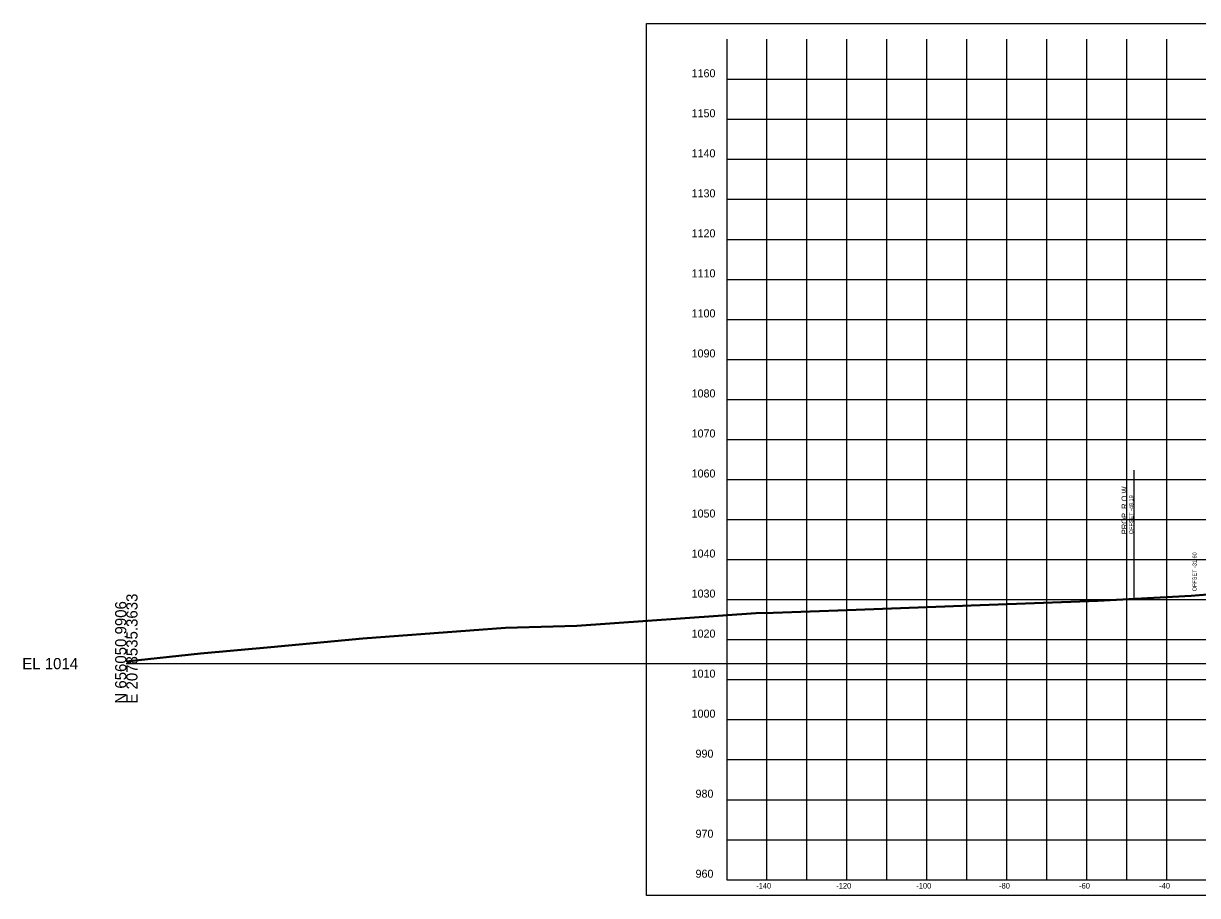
# Model space of a CAD drawing. Extents: x 1131015 to 1136271, y 133453 to 174329.
# Drawn here: x 1131014.8 to 1131308.1, y 155109.7 to 155327.6 of the extents above; entities that cross this region are included whole.
import ezdxf

# ---------------------------------------------------------------- set-up
doc = ezdxf.new("R2010")
doc.units = 0
for name, color, linetype in [('DESIGN - ROW - Right-of-Way and Easement Labels', 7, 'Continuous'), ('DESIGN - ROW - Right-of-Way Linework', 7, 'Continuous'), ('DESIGN - SHEET - Corner Text', 7, 'Continuous'), ('DESIGN - SHEET - Light Grid', 7, 'Continuous'), ('DESIGN - SHEET - Linework', 7, 'Continuous'), ('DESIGN - SHEET - Plot Shape', 7, 'Continuous'), ('DESIGN - TYPICAL - Slope Tie Text', 7, 'Continuous'), ('SURVEY - GROUND - Bottom of Topsoil Layer', 7, 'Continuous'), ('SURVEY - GROUND - Top of Ground', 7, 'Continuous')]:
    doc.layers.add(name, color=color, linetype=linetype)

msp = doc.modelspace()

# ---------------------------------------------------------------- linework, layer by layer
at = {"layer": 'DESIGN - ROW - Right-of-Way Linework'}
msp.add_line((1131292.27, 155183.98), (1131292.27, 155215.98), dxfattribs=at)
at = {"layer": 'DESIGN - SHEET - Light Grid'}
msp.add_line((1131040.46, 155167.66), (1131340.46, 155167.66), dxfattribs=at)
at = {"layer": 'DESIGN - SHEET - Linework'}
for p, q in [((1131200.46, 155113.66), (1131200.46, 155323.66)), ((1131210.46, 155113.66), (1131210.46, 155323.66)), ((1131220.46, 155113.66), (1131220.46, 155323.66)), ((1131230.46, 155113.66), (1131230.46, 155323.66)), ((1131240.46, 155113.66), (1131240.46, 155323.66)), ((1131250.46, 155113.66), (1131250.46, 155323.66)), ((1131260.46, 155113.66), (1131260.46, 155323.66)), ((1131270.46, 155113.66), (1131270.46, 155323.66)), ((1131280.46, 155113.66), (1131280.46, 155323.66)), ((1131290.46, 155113.66), (1131290.46, 155323.66)), ((1131300.46, 155113.66), (1131300.46, 155323.66)), ((1131190.46, 155313.66), (1131490.46, 155313.66)), ((1131190.46, 155303.66), (1131490.46, 155303.66)), ((1131190.46, 155293.66), (1131490.46, 155293.66)), ((1131190.46, 155283.66), (1131490.46, 155283.66)), ((1131190.46, 155273.66), (1131490.46, 155273.66)), ((1131190.46, 155263.66), (1131490.46, 155263.66)), ((1131190.46, 155253.66), (1131490.46, 155253.66)), ((1131190.46, 155243.66), (1131490.46, 155243.66)), ((1131190.46, 155233.66), (1131490.46, 155233.66)), ((1131190.46, 155223.66), (1131490.46, 155223.66)), ((1131190.46, 155213.66), (1131490.46, 155213.66)), ((1131190.46, 155203.66), (1131490.46, 155203.66)), ((1131190.46, 155193.66), (1131490.46, 155193.66)), ((1131190.46, 155183.66), (1131490.46, 155183.66)), ((1131190.46, 155173.66), (1131490.46, 155173.66)), ((1131190.46, 155163.66), (1131490.46, 155163.66)), ((1131190.46, 155153.66), (1131490.46, 155153.66)), ((1131190.46, 155143.66), (1131490.46, 155143.66)), ((1131190.46, 155133.66), (1131490.46, 155133.66)), ((1131190.46, 155123.66), (1131490.46, 155123.66))]:
    msp.add_line(p, q, dxfattribs=at)
msp.add_lwpolyline([(1131190.46, 155323.66), (1131190.46, 155113.66), (1131490.46, 155113.66), (1131490.46, 155323.66)], dxfattribs=at)
at = {"layer": 'DESIGN - SHEET - Plot Shape'}
msp.add_lwpolyline([(1131170.46, 155327.6), (1131510.46, 155327.6), (1131510.46, 155109.72), (1131170.46, 155109.72)], close=True, dxfattribs=at)
at = {"layer": 'SURVEY - GROUND - Bottom of Topsoil Layer'}
for p, q in [((1131306.49, 155184.53), (1131327.33, 155186.26)), ((1131220.57, 155180.94), (1131253.79, 155182.15)), ((1131253.79, 155182.15), (1131283.22, 155183.22)), ((1131283.22, 155183.22), (1131306.49, 155184.53)), ((1131153.05, 155177.04), (1131197.73, 155180.18)), ((1131197.73, 155180.18), (1131202.07, 155180.3)), ((1131202.07, 155180.3), (1131220.57, 155180.94)), ((1131099.53, 155173.89), (1131135.17, 155176.51)), ((1131135.17, 155176.51), (1131153.05, 155177.04)), ((1131076.57, 155171.65), (1131099.53, 155173.89)), ((1131059, 155170.12), (1131076.57, 155171.65)), ((1131040.46, 155168.13), (1131059, 155170.12))]:
    msp.add_line(p, q, dxfattribs=at)
at = {"layer": 'SURVEY - GROUND - Top of Ground'}
for p, q in [((1131306.49, 155184.78), (1131327.33, 155186.51)), ((1131220.57, 155181.19), (1131253.79, 155182.4)), ((1131253.79, 155182.4), (1131283.22, 155183.47)), ((1131283.22, 155183.47), (1131306.49, 155184.78)), ((1131153.05, 155177.29), (1131197.73, 155180.43)), ((1131197.73, 155180.43), (1131202.07, 155180.55)), ((1131202.07, 155180.55), (1131220.57, 155181.19)), ((1131099.53, 155174.14), (1131135.17, 155176.76)), ((1131135.17, 155176.76), (1131153.05, 155177.29)), ((1131076.57, 155171.9), (1131099.53, 155174.14)), ((1131040.46, 155168.38), (1131059, 155170.37)), ((1131059, 155170.37), (1131076.57, 155171.9))]:
    msp.add_line(p, q, dxfattribs=at)

# ---------------------------------------------------------------- texts
at = {"layer": 'DESIGN - ROW - Right-of-Way and Easement Labels'}
for s, height, p in [('PROP. R.O.W.', 1.4, (1131290.52, 155199.98)), ('OFFSET -48.19', 1, (1131292.02, 155199.98))]:
    msp.add_text(s, height=height, rotation=90, dxfattribs=at).set_placement(p)
at = {"layer": 'DESIGN - SHEET - Corner Text'}
for s, height, p in [('1160', 2, (1131181.7, 155314.16)), ('1150', 2, (1131181.7, 155304.16)), ('1140', 2, (1131181.7, 155294.16)), ('1130', 2, (1131181.7, 155284.16)), ('1120', 2, (1131181.7, 155274.16)), ('1110', 2, (1131181.7, 155264.16)), ('1100', 2, (1131181.7, 155254.16)), ('1090', 2, (1131181.7, 155244.16)), ('1080', 2, (1131181.7, 155234.16)), ('1070', 2, (1131181.7, 155224.16)), ('1060', 2, (1131181.7, 155214.16)), ('1050', 2, (1131181.7, 155204.16)), ('1040', 2, (1131181.7, 155194.16)), ('1030', 2, (1131181.7, 155184.16)), ('1020', 2, (1131181.7, 155174.16)), ('1010', 2, (1131181.7, 155164.16)), ('1000', 2, (1131181.7, 155154.16)), ('990', 2, (1131182.68, 155144.16)), ('980', 2, (1131182.68, 155134.16)), ('970', 2, (1131182.68, 155124.16)), ('960', 2, (1131182.68, 155114.16)), ('-140', 1.4, (1131197.83, 155111.46)), ('-120', 1.4, (1131217.83, 155111.46)), ('-100', 1.4, (1131237.83, 155111.46)), ('-80', 1.4, (1131258.51, 155111.46)), ('-60', 1.4, (1131278.51, 155111.46)), ('-40', 1.4, (1131298.51, 155111.46))]:
    msp.add_text(s, height=height, dxfattribs=at).set_placement(p)
at = {"layer": 'DESIGN - SHEET - Light Grid'}
for s, p in [('E 2078535.3633', (1131043.26, 155157.66)), ('N 656050.9906', (1131040.46, 155157.66))]:
    msp.add_text(s, height=2.8, rotation=90, dxfattribs=at).set_placement(p)
msp.add_text('EL 1014', height=2.8, dxfattribs=at).set_placement((1131014.46, 155166.26))
at = {"layer": 'DESIGN - TYPICAL - Slope Tie Text'}
msp.add_text('OFFSET -31.60', height=1, rotation=90, dxfattribs=at).set_placement((1131307.85, 155185.72))

doc.saveas('drawing.dxf')
